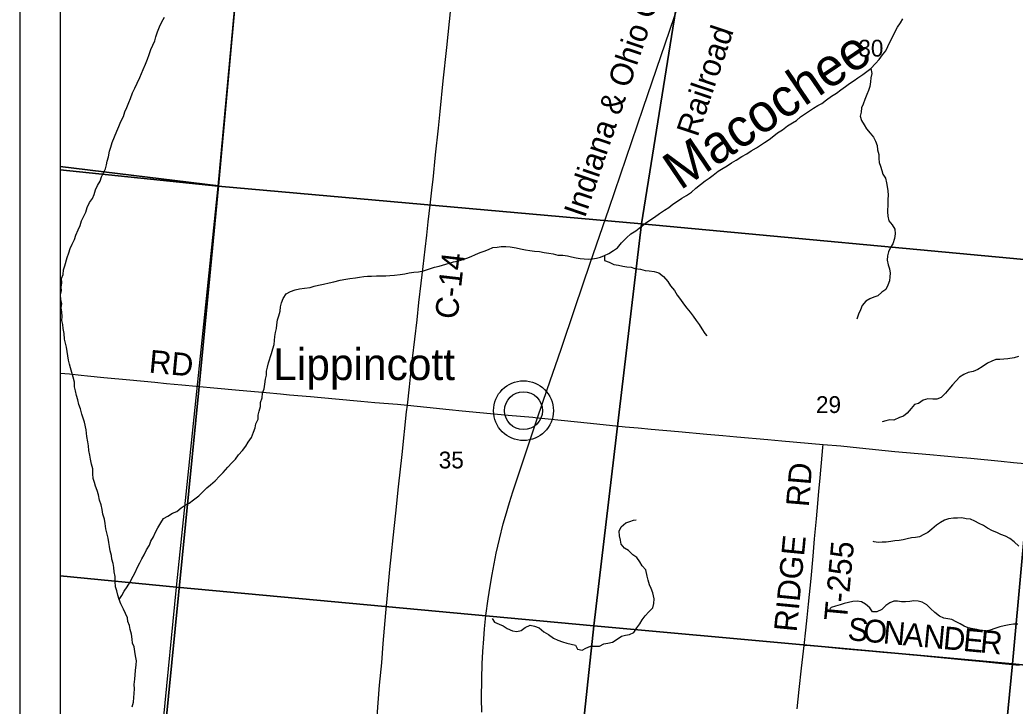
# Model space of a CAD drawing. Extents: x 831 to 1552, y 430 to 870.
# Drawn here: x 943.77 to 993.28, y 714.97 to 749.13 of the extents above; entities that cross this region are included whole.
import ezdxf

# ---------------------------------------------------------------- set-up
doc = ezdxf.new("R2010")
doc.units = 0
for name, color, linetype in [('GM_X_Corporation', 7, 'Continuous'), ('GM_X_County_Road', 7, 'Continuous'), ('GM_X_County_Road_Text', 7, 'Continuous'), ('GM_X_Major_River', 7, 'Continuous'), ('GM_X_Minor_River', 7, 'Continuous'), ('GM_X_Minor_River_Text', 7, 'Continuous'), ('GM_X_Rail_Line', 7, 'Continuous'), ('GM_X_Rail_Line_Text', 7, 'Continuous'), ('GM_X_Section_Text', 7, 'Continuous'), ('GM_X_Township_Road', 7, 'Continuous'), ('GM_X_Township_Road_Text', 7, 'Continuous'), ('GM_X_Unincorporated', 7, 'Continuous'), ('GM_X_Unincorporated_Location', 7, 'Continuous'), ('GM_X_Unincorporated_Text', 7, 'Continuous'), ('SH_Data', 7, 'Continuous')]:
    doc.layers.add(name, color=color, linetype=linetype)

msp = doc.modelspace()

# ---------------------------------------------------------------- linework, layer by layer
at = {"layer": 'GM_X_Corporation'}
for points in [[(958.1, 786.938), (945.766, 786.938), (945.766, 741.831), (953.653, 740.871), (955.451, 760.717), (956.56, 771.006), (957.479, 781.045), (957.492, 781.063), (957.507, 781.085), (957.522, 781.111), (957.532, 781.136), (957.541, 781.164), (957.55, 781.197), (957.556, 781.228), (957.562, 781.276), (957.568, 781.33), (957.577, 781.435), (957.589, 781.599), (957.656, 782.366), (957.749, 783.356), (957.89, 784.782), (957.984, 785.755), (958.044, 786.336)], [(945.766, 761.978), (945.766, 741.664), (953.634, 740.857), (955.51, 761.115)], [(977.893, 758.996), (974.695, 738.984), (953.634, 740.857), (955.51, 761.115)], [(996.953, 757.185), (994.975, 737.085), (974.695, 738.984), (977.893, 758.996)], [(945.766, 741.831), (945.766, 658.183), (947.763, 681.071), (949.971, 703.401), (952.689, 730.885), (953.653, 740.871)], [(945.766, 741.664), (945.766, 721.457), (951.55, 720.891), (953.634, 740.857)], [(953.634, 740.857), (974.695, 738.984), (972.322, 718.961), (951.55, 720.891)], [(974.695, 738.984), (994.975, 737.085), (993.147, 717.069), (972.322, 718.961)], [(994.975, 737.085), (1015.357, 735.031), (1013.944, 715), (993.147, 717.069)], [(945.766, 721.457), (945.766, 701.429), (949.612, 701.081), (951.55, 720.891)], [(972.322, 718.961), (970.228, 699.411), (949.612, 701.081), (951.55, 720.891)], [(993.147, 717.069), (991.236, 697.554), (970.228, 699.411), (972.322, 718.961)], [(993.147, 717.069), (1013.944, 715), (1011.587, 695.769), (991.236, 697.554)]]:
    msp.add_lwpolyline(points, close=True, dxfattribs=at)
msp.add_lwpolyline([(957.479, 781.045), (956.56, 771.006), (955.451, 760.717), (953.653, 740.871), (952.689, 730.885), (949.971, 703.401), (947.763, 681.071), (945.766, 658.183), (945.766, 650.938), (1069.909, 650.938), (1070.34, 654.531), (1072.813, 675.454), (1078.126, 715.958), (1081.227, 740.59), (1081.766, 744.853), (1081.766, 786.938)], dxfattribs=at)
at = {"layer": 'GM_X_County_Road'}
for points in [[(963.043, 729.951), (963.14, 730.858), (963.201, 731.36), (963.301, 732.269), (963.523, 734.194), (963.62, 735.069), (963.735, 736.019), (963.829, 736.846), (963.929, 737.716), (964.005, 738.408), (964.082, 739.077), (964.181, 739.907), (964.276, 740.808), (964.321, 741.191), (964.449, 742.418), (964.587, 743.741), (964.668, 744.571), (964.825, 746.089), (965.003, 747.758), (965.136, 749.053), (965.307, 750.7)], [(945.766, 731.552), (945.775, 731.551), (946.237, 731.505), (946.816, 731.446), (947.128, 731.416), (947.944, 731.332), (949.228, 731.209), (950.472, 731.089), (951.066, 731.03), (951.824, 730.959), (952.539, 730.888), (952.694, 730.875)], [(952.694, 730.875), (953.415, 730.81), (954.681, 730.691), (956.018, 730.576), (956.723, 730.51), (957.175, 730.471), (958.226, 730.377), (959.47, 730.264), (960.73, 730.147), (961.43, 730.089), (962.554, 729.994), (963.043, 729.951)], [(961.517, 714.233), (961.591, 715.127), (961.663, 716.006), (961.765, 717.12), (961.836, 718.087), (961.968, 719.609), (962.032, 720.315), (962.174, 721.762), (962.256, 722.553), (962.34, 723.344), (962.47, 724.58), (962.606, 725.878), (962.777, 727.497), (963.007, 729.61), (963.043, 729.951)], [(963.043, 729.951), (964.015, 729.851), (965.116, 729.742), (965.771, 729.676), (968.049, 729.456), (969.277, 729.345)], [(969.277, 729.345), (969.398, 729.334), (970.7, 729.203), (972.15, 729.055), (973.875, 728.879), (974.53, 728.817), (975.173, 728.759), (976.534, 728.639), (977.932, 728.514), (978.737, 728.441), (979.43, 728.378), (980.977, 728.237), (981.679, 728.174), (983.722, 727.993)], [(983.722, 727.993), (984.604, 727.918), (985.532, 727.828), (987.3, 727.649), (989.033, 727.492), (990.468, 727.36), (991.066, 727.306), (992.584, 727.163), (993.202, 727.103), (993.759, 727.048), (994.316, 726.996), (994.959, 726.933), (995.466, 726.885), (996.023, 726.832), (996.715, 726.762), (997.851, 726.652), (999.051, 726.537), (1000.56, 726.391), (1001.711, 726.28), (1003.232, 726.134), (1004.39, 726.022)]]:
    msp.add_lwpolyline(points, dxfattribs=at)
at = {"layer": 'GM_X_Major_River'}
for points in [[(949.603, 745.984), (949.732, 746.261), (949.896, 746.666), (950.017, 746.921), (950.116, 747.169), (950.191, 747.41), (950.274, 747.65), (950.379, 747.868), (950.484, 748.085), (950.528, 748.289), (950.619, 748.529), (950.717, 748.785), (950.823, 749.04), (950.952, 749.272)], [(948.221, 722.909), (948.189, 723.107), (948.158, 723.335), (948.103, 723.533), (948.035, 723.793), (948.005, 724.066), (947.974, 724.272), (947.897, 724.517), (947.859, 724.76), (947.805, 724.989), (947.721, 725.219), (947.668, 725.485), (947.614, 725.699), (947.529, 725.914), (947.474, 726.105), (947.412, 726.304), (947.396, 726.531), (947.388, 726.774), (947.334, 727.01), (947.28, 727.254), (947.241, 727.46), (947.202, 727.689), (947.179, 727.924), (947.14, 728.13), (947.094, 728.389), (947.058, 728.716), (946.978, 729.097), (946.916, 729.296), (946.846, 729.495), (946.778, 729.77), (946.701, 729.984), (946.648, 730.221), (946.586, 730.435), (946.531, 730.656), (946.484, 730.862), (946.476, 731.098), (946.408, 731.35), (946.346, 731.572), (946.277, 731.801), (946.237, 731.999), (946.19, 732.198), (946.158, 732.411), (946.08, 732.83), (946.033, 733.044), (945.978, 733.243), (945.963, 733.516), (945.918, 733.768), (945.901, 733.966), (945.846, 734.157), (945.867, 734.368), (945.851, 734.574), (945.827, 734.802), (945.855, 734.991), (945.809, 735.212), (945.793, 735.44), (945.829, 735.636), (945.827, 735.826), (945.849, 736.045), (945.84, 736.258), (945.922, 736.46), (945.943, 736.687), (945.995, 736.883), (946.121, 737.296), (946.196, 737.529), (946.263, 737.755), (946.361, 737.972), (946.481, 738.196), (946.556, 738.421), (946.663, 738.676), (946.76, 738.901), (946.827, 739.119), (946.932, 739.328), (947.038, 739.553), (947.12, 739.786), (947.234, 740.033), (947.384, 740.241), (947.466, 740.436), (947.533, 740.669), (947.631, 740.894), (947.751, 741.103), (947.833, 741.313), (947.931, 741.522), (948.02, 741.717), (948.079, 741.913), (948.107, 742.102), (948.182, 742.32), (948.228, 742.599), (948.294, 742.795), (948.362, 743.028), (948.469, 743.306), (948.584, 743.591), (948.682, 743.831), (948.795, 744.078), (948.916, 744.325), (948.984, 744.559), (949.081, 744.776), (949.18, 745.016), (949.261, 745.219), (949.368, 745.504), (949.489, 745.736), (949.603, 745.984)], [(949.343, 714.93), (949.41, 715.163), (949.44, 715.405), (949.454, 715.601), (949.461, 715.828), (949.452, 716.041), (949.49, 716.312), (949.504, 716.524), (949.51, 716.743), (949.557, 717.015), (949.57, 717.219), (949.524, 717.463), (949.485, 717.683), (949.447, 717.912), (949.376, 718.103), (949.352, 718.301), (949.314, 718.544), (949.252, 718.781), (949.213, 718.987), (949.143, 719.178), (949.126, 719.368), (949.025, 719.575), (948.926, 719.79), (948.789, 720.052), (948.705, 720.274), (948.643, 720.495), (948.596, 720.709), (948.526, 720.9), (948.511, 721.166), (948.511, 721.416), (948.457, 721.652), (948.434, 721.872), (948.401, 722.07), (948.347, 722.276), (948.322, 722.474), (948.261, 722.696), (948.221, 722.909)]]:
    msp.add_lwpolyline(points, dxfattribs=at)
at = {"layer": 'GM_X_Minor_River'}
for points in [[(986.51, 747.153), (986.677, 747.399), (986.849, 747.591), (986.947, 747.809), (987.06, 748.049), (987.173, 748.266), (987.301, 748.521), (987.43, 748.76), (987.581, 748.984), (987.685, 749.178)], [(963.595, 736.594), (963.847, 736.639), (964.2, 736.75), (964.391, 736.813), (964.621, 736.874), (965.126, 737.025), (965.34, 737.08), (965.539, 737.127), (965.753, 737.189), (965.998, 737.265), (966.221, 737.356), (966.437, 737.456), (966.667, 737.555), (966.866, 737.61), (967.082, 737.702), (967.289, 737.795), (967.503, 737.818), (967.701, 737.843), (967.936, 737.843), (968.163, 737.829), (968.45, 737.782), (968.669, 737.73), (968.918, 737.677), (969.129, 737.648), (969.372, 737.625), (969.621, 737.595), (969.847, 737.543), (970.074, 737.521), (970.301, 737.476), (970.527, 737.424), (970.777, 737.416), (971.004, 737.379), (971.207, 737.327), (971.434, 737.29), (971.638, 737.254), (971.842, 737.24), (972.039, 737.219), (972.252, 737.243), (972.45, 737.267), (972.649, 737.314), (972.841, 737.399), (973.057, 737.507), (973.297, 737.651), (973.498, 737.782), (973.687, 738.034), (973.938, 738.284), (974.163, 738.475), (974.411, 738.634), (974.66, 738.824), (974.893, 739.015), (975.102, 739.153), (975.342, 739.312), (975.59, 739.487), (975.83, 739.654), (976.047, 739.792), (976.256, 739.953), (976.481, 740.098), (976.69, 740.251), (976.929, 740.38), (977.177, 740.555), (977.388, 740.754), (977.621, 740.929), (977.862, 741.119), (978.055, 741.243), (978.257, 741.396), (978.498, 741.594), (978.746, 741.746), (978.947, 741.869), (979.171, 742.014), (979.403, 742.152), (979.681, 742.326), (979.928, 742.455), (980.153, 742.608), (980.415, 742.759), (980.802, 743.021), (981.042, 743.181), (981.268, 743.357), (981.462, 743.503), (981.709, 743.663), (981.958, 743.86), (982.197, 744.005), (982.398, 744.128), (982.601, 744.312), (982.849, 744.472), (983.042, 744.603), (983.251, 744.741), (983.467, 744.864), (983.66, 744.965), (983.893, 745.148), (984.149, 745.33), (984.396, 745.482), (984.614, 745.651), (984.839, 745.811), (985.041, 745.965), (985.265, 746.118), (985.459, 746.249), (985.699, 746.416), (985.893, 746.555), (986.102, 746.709), (986.33, 746.953), (986.51, 747.153)], [(986.102, 746.709), (986.156, 746.456), (986.104, 746.252), (986.075, 746.04), (986.046, 745.821), (985.987, 745.617), (985.898, 745.422), (985.799, 745.159), (985.724, 744.941), (985.635, 744.746), (985.614, 744.541), (985.569, 744.33), (985.639, 744.123), (985.769, 743.906), (985.878, 743.713), (986.069, 743.494), (986.23, 743.292), (986.323, 743.099), (986.415, 742.876), (986.438, 742.655), (986.493, 742.433), (986.494, 742.228), (986.511, 742.037), (986.582, 741.845), (986.644, 741.638), (986.699, 741.447), (986.822, 741.253), (986.884, 741.024), (986.909, 740.833), (986.94, 740.627), (986.957, 740.406), (986.943, 740.186), (986.944, 739.974), (986.932, 739.579), (986.941, 739.351), (986.987, 739.13), (987.156, 738.92), (987.286, 738.718), (987.317, 738.482), (987.28, 738.241), (987.189, 737.985), (987.084, 737.791), (986.98, 737.582), (986.921, 737.386), (986.907, 737.174), (986.96, 736.93), (987.023, 736.738), (987.062, 736.525), (987.049, 736.335), (987.028, 736.146), (986.953, 735.929), (986.841, 735.712), (986.647, 735.574), (986.444, 735.39), (986.245, 735.328), (986.045, 735.243), (985.852, 735.12), (985.671, 734.905), (985.588, 734.688), (985.484, 734.486), (985.424, 734.276), (985.408, 734.238)], [(972.841, 737.399), (972.857, 737.156), (973.089, 737.066), (973.306, 736.961), (973.54, 736.915), (973.759, 736.863), (973.956, 736.842), (974.168, 736.828), (974.363, 736.754), (974.643, 736.723), (974.876, 736.655), (975.073, 736.642), (975.315, 736.597), (975.548, 736.536), (975.786, 736.355), (975.999, 736.113), (976.129, 735.897), (976.327, 735.663), (976.464, 735.432), (976.632, 735.214), (976.785, 734.99), (976.946, 734.78), (977.115, 734.578), (977.268, 734.377), (977.406, 734.16), (977.567, 733.958), (977.689, 733.742), (977.842, 733.518), (977.938, 733.409)], [(948.705, 720.274), (948.84, 720.482), (948.96, 720.683), (949.103, 720.898), (949.239, 721.129), (949.407, 721.435), (949.52, 721.651), (949.602, 721.853), (949.73, 722.099), (949.827, 722.293), (949.94, 722.494), (950.068, 722.74), (950.212, 722.978), (950.279, 723.181), (950.406, 723.389), (950.496, 723.598), (950.625, 723.837), (950.776, 724.09), (950.904, 724.306), (951.12, 724.428), (951.352, 724.573), (951.575, 724.664), (951.793, 724.84), (951.987, 724.97), (952.187, 725.07), (952.397, 725.231), (952.661, 725.442), (952.856, 725.611), (953.06, 725.832), (953.254, 725.985), (953.48, 726.183), (953.699, 726.411), (953.872, 726.603), (954.107, 726.868), (954.311, 727.074), (954.491, 727.266), (954.649, 727.481), (954.838, 727.695), (955.004, 727.91), (955.123, 728.103), (955.282, 728.34), (955.389, 728.602), (955.471, 728.827), (955.5, 729.023), (955.62, 729.254), (955.627, 729.459), (955.663, 729.655), (955.73, 729.88), (955.736, 730.077), (955.811, 730.317), (955.841, 730.543), (955.916, 730.768), (955.945, 730.995), (955.983, 731.244), (956.027, 731.44), (956.041, 731.651), (956.077, 731.847), (956.136, 732.05), (956.287, 732.516), (956.347, 732.756), (956.414, 732.966), (956.427, 733.171), (956.441, 733.367), (956.485, 733.571), (956.529, 733.767), (956.549, 733.956), (956.587, 734.197), (956.646, 734.4), (956.706, 734.626), (956.735, 734.845), (956.786, 735.04), (956.861, 735.265), (957.02, 735.496), (957.228, 735.611), (957.466, 735.695), (957.68, 735.749), (957.931, 735.772), (958.214, 735.816), (958.405, 735.879), (958.619, 735.925), (958.871, 735.971), (959.146, 736.046), (959.391, 736.091), (959.697, 736.181), (959.979, 736.225), (960.185, 736.257), (960.459, 736.294), (960.665, 736.326), (960.871, 736.35), (961.061, 736.367), (961.258, 736.369), (961.51, 736.391), (961.707, 736.393), (961.972, 736.385), (962.178, 736.409), (962.399, 736.425), (962.688, 736.447), (962.909, 736.493), (963.138, 736.539), (963.367, 736.563), (963.595, 736.594)], [(993.443, 732.369), (993.229, 732.308), (992.916, 732.256), (992.719, 732.247), (992.521, 732.23), (992.316, 732.229), (992.116, 732.144), (991.9, 732.037), (991.637, 731.855), (991.428, 731.725), (991.183, 731.634), (990.938, 731.573), (990.723, 731.481), (990.514, 731.343), (990.168, 730.96), (989.972, 730.753), (989.814, 730.546), (989.603, 730.34), (989.388, 730.241), (989.183, 730.247), (988.941, 730.269), (988.696, 730.201), (988.463, 730.041), (988.264, 729.979), (988.099, 729.787), (987.91, 729.558), (987.716, 729.405), (987.524, 729.342), (987.239, 729.207), (987.043, 729.228), (986.851, 729.173), (986.66, 729.118)], [(993.458, 722.933), (993.229, 723.151), (993.006, 723.309), (992.805, 723.436), (992.565, 723.519), (992.37, 723.615), (992.16, 723.697), (991.906, 723.833), (991.697, 723.953), (991.495, 724.057), (991.271, 724.17), (991.054, 724.267), (990.842, 724.288), (990.631, 724.348), (990.403, 724.317), (990.206, 724.33), (989.969, 724.292), (989.762, 724.222), (989.562, 724.115), (989.36, 723.969), (989.134, 723.772), (988.939, 723.604), (988.731, 723.504), (988.515, 723.39), (988.325, 723.357), (988.127, 723.341), (987.905, 723.302), (987.714, 723.247), (987.501, 723.216), (987.295, 723.199), (987.097, 723.167), (986.861, 723.136), (986.663, 723.135), (986.465, 723.11), (986.262, 723.154), (986.209, 723.163)], [(967.256, 719.331), (967.372, 719.139), (967.605, 719.056), (967.807, 718.967), (968, 718.84), (968.278, 718.711), (968.489, 718.69), (968.703, 718.729), (968.905, 718.874), (969.159, 719.003), (969.37, 718.944), (969.603, 718.869), (969.824, 718.658), (970.071, 718.529), (970.316, 718.356), (970.525, 718.251), (970.758, 718.161), (970.969, 718.102), (971.195, 718.057), (971.399, 718.006), (971.514, 717.806), (971.733, 717.754), (971.925, 717.847), (972.148, 717.954), (972.383, 717.947), (972.604, 717.948), (972.812, 718.07), (973.011, 718.11), (973.247, 718.148), (973.472, 718.3), (973.696, 718.445), (973.895, 718.492), (974.101, 718.531), (974.302, 718.639), (974.46, 718.869), (974.61, 719.061), (974.723, 719.269), (974.865, 719.462), (975.061, 719.668), (975.249, 719.859), (975.308, 720.076), (975.315, 720.311), (975.248, 720.6), (975.164, 720.822), (975.094, 721.013), (975.025, 721.242), (974.977, 721.44), (974.903, 721.752), (974.727, 721.954), (974.604, 722.155), (974.466, 722.371), (974.258, 722.505), (974.044, 722.708), (973.843, 722.835), (973.682, 723.037), (973.642, 723.227), (973.603, 723.448), (973.587, 723.683), (973.685, 723.899), (973.911, 724.097), (974.102, 724.159), (974.294, 724.221), (974.423, 724.24)], [(993.41, 719.041), (993.19, 719.047), (992.984, 719.016), (992.732, 718.97), (992.518, 718.909), (992.265, 718.825), (992.035, 718.741), (991.813, 718.703), (991.579, 718.74), (991.375, 718.776), (991.179, 718.82), (990.945, 718.857), (990.75, 718.946), (990.541, 719.066), (990.347, 719.17), (990.13, 719.274), (989.934, 719.318), (989.738, 719.354), (989.513, 719.451), (989.283, 719.632), (989.069, 719.827), (988.877, 720.007), (988.653, 720.135), (988.458, 720.201), (988.231, 720.215), (988.039, 720.168), (987.819, 720.167), (987.629, 720.165), (987.433, 720.186), (987.243, 720.192), (987.043, 720.107), (986.85, 719.976), (986.639, 719.771), (986.393, 719.665), (986.18, 719.664), (986.049, 719.864), (985.827, 720.045), (985.633, 720.156), (985.414, 720.185), (985.209, 720.176), (984.987, 720.13), (984.765, 720.076), (984.566, 720.006), (984.344, 719.937), (984.129, 719.876), (984.052, 719.81)]]:
    msp.add_lwpolyline(points, dxfattribs=at)
at = {"layer": 'GM_X_Rail_Line'}
msp.add_lwpolyline([(966.754, 714.671), (966.737, 715.348), (966.741, 716.323), (966.764, 717.075), (966.797, 717.691), (966.839, 718.324), (966.886, 718.82), (966.953, 719.48), (967.057, 720.307), (967.158, 720.938), (967.254, 721.519), (967.303, 721.78), (967.466, 722.59), (967.619, 723.276), (967.812, 724.042), (967.923, 724.429), (968.115, 725.111), (968.282, 725.634), (969.522, 729.324), (970.005, 730.728), (970.689, 732.742), (971.392, 734.813), (972.143, 737.013), (973.077, 739.757), (974.776, 744.729), (976.758, 750.569)], dxfattribs=at)
at = {"layer": 'GM_X_Township_Road'}
for points in [[(982.776, 717.992), (982.86, 718.742), (982.93, 719.372), (983, 720.039), (983.124, 721.326), (983.228, 722.44), (983.303, 723.294), (983.392, 724.291), (983.464, 725.048), (983.52, 725.67), (983.563, 726.152), (983.694, 727.638), (983.711, 727.861), (983.722, 727.993)], [(982.435, 714.838), (982.536, 715.789), (982.656, 716.864), (982.776, 717.992)], [(993.474, 716.997), (992.46, 717.096), (991.669, 717.173), (990.766, 717.263), (990.098, 717.329), (989.74, 717.363), (988.564, 717.474), (988.007, 717.523), (987.487, 717.57), (987.091, 717.604), (986.695, 717.64), (986.187, 717.685), (984.816, 717.799), (983.824, 717.895), (982.902, 717.98), (982.776, 717.992)]]:
    msp.add_lwpolyline(points, dxfattribs=at)
at = {"layer": 'GM_X_Unincorporated'}
for radius in [1.488, 0.943]:
    msp.add_circle((968.818, 729.675), radius, dxfattribs=at)
at = {"layer": 'GM_X_Unincorporated_Location'}
msp.add_line((968.818, 729.675), (968.818, 729.675), dxfattribs=at)
at = {"layer": 'SH_Data'}
for p, q in [((943.766, 788.938), (943.766, 648.938)), ((945.766, 786.938), (945.766, 650.938))]:
    msp.add_line(p, q, dxfattribs=at)

# ---------------------------------------------------------------- texts
at = {"layer": 'GM_X_County_Road_Text'}
for s, rotation, p in [('C-14', 83.5118, (965.535, 734.195)), ('RD', 354.5844, (950.153, 731.578))]:
    msp.add_text(s, height=1.1364, rotation=rotation, dxfattribs=at).set_placement(p)
at = {"layer": 'GM_X_Minor_River_Text'}
msp.add_text('Macochee', height=1.8923, rotation=34.1303, dxfattribs=at).set_placement((976.614, 740.622))
at = {"layer": 'GM_X_Rail_Line_Text'}
for s, height, rotation, p in [('Indiana & Ohio Central', 1.13258, 71.2044, (971.871, 739.23)), ('Railroad', 1.1326, 71.2812, (977.48, 743.259))]:
    msp.add_text(s, height=height, rotation=rotation, dxfattribs=at).set_placement(p)
at = {"layer": 'GM_X_Section_Text'}
for s, p in [('30', (985.479, 747.302)), ('29', (983.371, 729.56)), ('35', (964.604, 726.802))]:
    msp.add_text(s, height=0.8371, rotation=0, dxfattribs=at).set_placement(p)
at = {"layer": 'GM_X_Township_Road_Text'}
for s, height, rotation, p in [('RD', 1.1364, 85.1948, (983.009, 724.857)), ('RIDGE', 1.1364, 84.4868, (982.409, 718.627)), ('T-255', 1.1364, 84.6787, (984.902, 719.169)), ('S', 1.136, 354.6038, (984.914, 718.262)), ('O', 1.136, 354.6008, (985.677, 718.19)), ('N', 1.136, 354.6012, (986.673, 718.096)), ('A', 1.136, 354.6049, (987.668, 718.002)), ('N', 1.136, 354.6008, (988.664, 717.908)), ('D', 1.136, 354.6029, (989.659, 717.814)), ('E', 1.136, 354.6007, (990.655, 717.72)), ('R', 1.136, 354.5904, (991.501, 717.64))]:
    msp.add_text(s, height=height, rotation=rotation, dxfattribs=at).set_placement(p)
at = {"layer": 'GM_X_Unincorporated_Text'}
msp.add_text('Lippincott', height=1.5795, rotation=0, dxfattribs=at).set_placement((956.371, 731.2))

doc.saveas('drawing.dxf')
